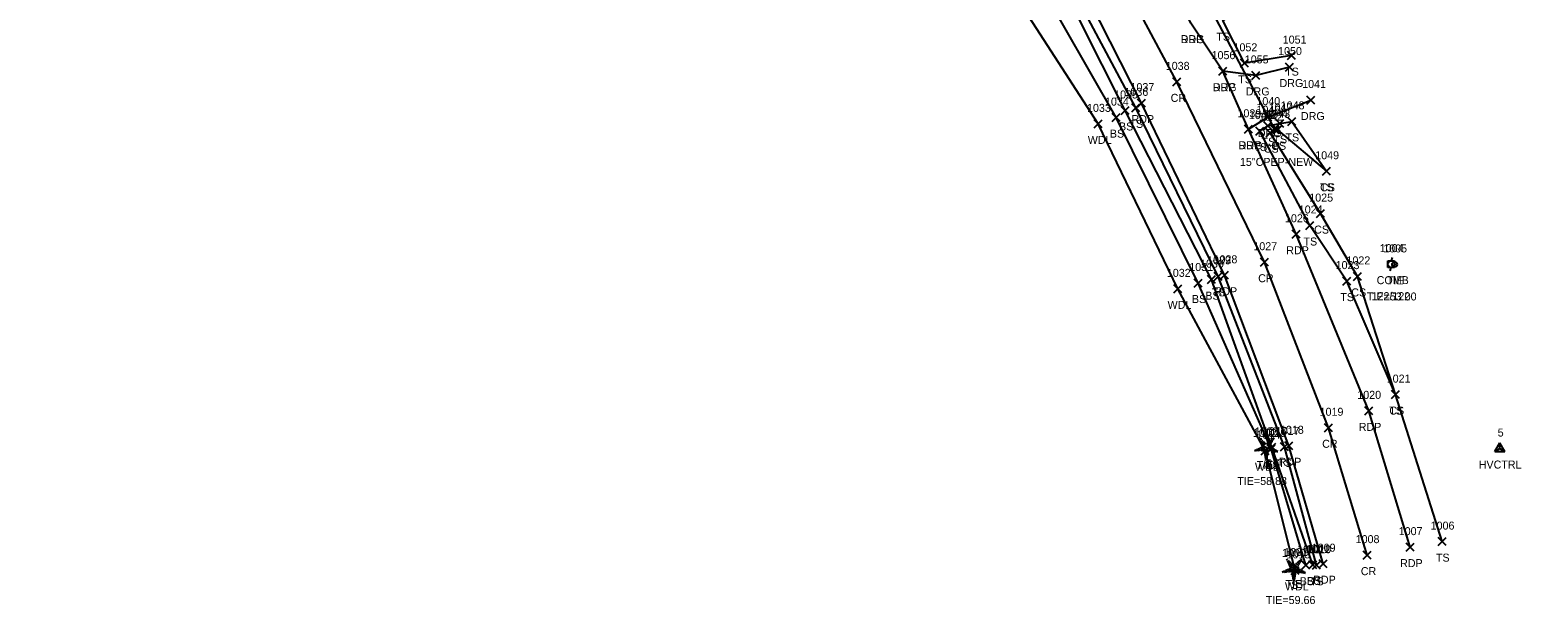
# Model space of a CAD drawing. Extents: x 1501299 to 1502485, y 381423 to 383765.
# Drawn here: x 1501626.4 to 1501999.1, y 382706.4 to 382849.9 of the extents above; entities that cross this region are included whole.
import ezdxf

# ---------------------------------------------------------------- set-up
doc = ezdxf.new("R2010")
doc.units = 0
for name, color, linetype in [('C_A', 7, 'Continuous'), ('C_C', 7, 'Continuous'), ('C_I', 7, 'Continuous'), ('CBP', 7, 'Continuous'), ('CPSM', 7, 'Continuous'), ('D_A', 7, 'Continuous'), ('D_C', 7, 'Continuous'), ('D_I', 7, 'Continuous'), ('D_TIC', 7, 'Continuous'), ('DCP', 7, 'Continuous'), ('L_A', 7, 'Continuous'), ('L_I', 7, 'Continuous'), ('L_TIC', 7, 'Continuous'), ('LAWA', 7, 'Continuous'), ('LELB', 7, 'Continuous'), ('LTC', 7, 'Continuous'), ('P_A', 7, 'Continuous'), ('P_I', 7, 'Continuous'), ('P_TIC', 7, 'Continuous'), ('PET', 7, 'Continuous'), ('PRC', 7, 'Continuous'), ('R_A', 7, 'Continuous'), ('R_I', 7, 'Continuous'), ('R_TIC', 7, 'Continuous'), ('RDG', 7, 'Continuous'), ('U_A', 7, 'Continuous'), ('U_C', 7, 'Continuous'), ('U_I', 7, 'Continuous'), ('UP', 7, 'Continuous')]:
    doc.layers.add(name, color=color, linetype=linetype)

msp = doc.modelspace()

# ---------------------------------------------------------------- linework, layer by layer
at = {"layer": 'CBP'}
for centre, radius in [((1501967.5, 382791.3), 0.625), ((1501967.5, 382791.3), 0.0833), ((1501934.94, 382745.18), 0.625), ((1501934.94, 382745.18), 0.0833), ((1501942.17, 382715.43), 0.625), ((1501942.17, 382715.43), 0.0833)]:
    msp.add_circle(centre, radius, dxfattribs=at)
at = {"layer": 'CPSM'}
for p, q in [((1501992.57, 382744.57), (1501993.82, 382746.73)), ((1501992.57, 382744.57), (1501993.82, 382745.29)), ((1501992.57, 382744.57), (1501995.07, 382744.57)), ((1501995.07, 382744.57), (1501993.82, 382746.73)), ((1501993.82, 382745.29), (1501993.82, 382746.73)), ((1501993.82, 382745.29), (1501993.82, 382745.29)), ((1501993.82, 382745.29), (1501995.07, 382744.57))]:
    msp.add_line(p, q, dxfattribs=at)
at = {"layer": 'D_TIC'}
for points in [[(1501936.68, 382823.93), (1501938.68, 382825.93)], [(1501938.68, 382823.93), (1501936.68, 382825.93)]]:
    msp.add_lwpolyline(points, dxfattribs=at)
at = {"layer": 'DCP'}
msp.add_lwpolyline([(1501937.68, 382824.93), (1501912.68, 382872.03)], dxfattribs=at)
at = {"layer": 'L_TIC'}
for points in [[(1501929, 382840.57), (1501931, 382842.57)], [(1501931, 382840.57), (1501929, 382842.57)], [(1501940.73, 382842.49), (1501942.73, 382844.49)], [(1501942.73, 382842.49), (1501940.73, 382844.49)], [(1501899.17, 382828.78), (1501901.17, 382830.78)], [(1501901.17, 382828.78), (1501899.17, 382830.78)], [(1501901.81, 382829.43), (1501903.81, 382831.43)], [(1501903.81, 382829.43), (1501901.81, 382831.43)], [(1501892.39, 382825.43), (1501894.39, 382827.43)], [(1501894.39, 382825.43), (1501892.39, 382827.43)], [(1501896.88, 382826.99), (1501898.88, 382828.99)], [(1501898.88, 382826.99), (1501896.88, 382828.99)], [(1501934.81, 382824.97), (1501936.81, 382826.97)], [(1501936.81, 382824.97), (1501934.81, 382826.97)], [(1501937.79, 382825.56), (1501939.79, 382827.56)], [(1501939.79, 382825.56), (1501937.79, 382827.56)], [(1501940.8, 382826.05), (1501942.8, 382828.05)], [(1501942.8, 382826.05), (1501940.8, 382828.05)], [(1501932.85, 382823.63), (1501934.85, 382825.63)], [(1501934.85, 382823.63), (1501932.85, 382825.63)], [(1501935.36, 382823.23), (1501937.36, 382825.23)], [(1501937.36, 382823.23), (1501935.36, 382825.23)], [(1501937.22, 382823.94), (1501939.22, 382825.94)], [(1501939.22, 382823.94), (1501937.22, 382825.94)], [(1501949.44, 382813.58), (1501951.44, 382815.58)], [(1501951.44, 382813.58), (1501949.44, 382815.58)], [(1501949.44, 382813.58), (1501951.44, 382815.58)], [(1501951.44, 382813.58), (1501949.44, 382815.58)], [(1501947.94, 382803.01), (1501949.94, 382805.01)], [(1501949.94, 382803.01), (1501947.94, 382805.01)], [(1501945.31, 382800.03), (1501947.31, 382802.03)], [(1501947.31, 382800.03), (1501945.31, 382802.03)], [(1501922.41, 382787.32), (1501924.41, 382789.32)], [(1501924.41, 382787.32), (1501922.41, 382789.32)], [(1501957.23, 382787.31), (1501959.23, 382789.31)], [(1501959.23, 382787.31), (1501957.23, 382789.31)], [(1501912.34, 382784.2), (1501914.34, 382786.2)], [(1501914.34, 382784.2), (1501912.34, 382786.2)], [(1501917.39, 382785.66), (1501919.39, 382787.66)], [(1501919.39, 382785.66), (1501917.39, 382787.66)], [(1501920.74, 382786.5), (1501922.74, 382788.5)], [(1501922.74, 382786.5), (1501920.74, 382788.5)], [(1501954.52, 382786.13), (1501956.52, 382788.13)], [(1501956.52, 382786.13), (1501954.52, 382788.13)], [(1501966.73, 382757.77), (1501968.73, 382759.77)], [(1501968.73, 382757.77), (1501966.73, 382759.77)], [(1501966.73, 382757.77), (1501968.73, 382759.77)], [(1501968.73, 382757.77), (1501966.73, 382759.77)], [(1501934.18, 382743.72), (1501936.18, 382745.72)], [(1501936.18, 382743.72), (1501934.18, 382745.72)], [(1501935.67, 382744.19), (1501937.67, 382746.19)], [(1501937.67, 382744.19), (1501935.67, 382746.19)], [(1501935.79, 382744.62), (1501937.79, 382746.62)], [(1501937.79, 382744.62), (1501935.79, 382746.62)], [(1501939, 382744.7), (1501941, 382746.7)], [(1501941, 382744.7), (1501939, 382746.7)], [(1501978.41, 382721.03), (1501980.41, 382723.03)], [(1501980.41, 382721.03), (1501978.41, 382723.03)], [(1501941.68, 382713.84), (1501943.68, 382715.84)], [(1501943.68, 382713.84), (1501941.68, 382715.84)], [(1501944.34, 382715.14), (1501946.34, 382717.14)], [(1501946.34, 382715.14), (1501944.34, 382717.14)], [(1501946.07, 382715.2), (1501948.07, 382717.2)], [(1501948.07, 382715.2), (1501946.07, 382717.2)], [(1501946.96, 382715.12), (1501948.96, 382717.12)], [(1501948.96, 382715.12), (1501946.96, 382717.12)]]:
    msp.add_lwpolyline(points, dxfattribs=at)
at = {"layer": 'LAWA'}
msp.add_lwpolyline([(1501942.68, 382714.84), (1501935.18, 382744.72), (1501913.34, 382785.2), (1501893.39, 382826.43), (1501865.29, 382869.92), (1501854.75, 382888.13), (1501835.93, 382927.55), (1501822.23, 382953.47), (1501796.61, 382993.04), (1501779.61, 383024.31), (1501754.16, 383064.05), (1501733.53, 383095.14)], dxfattribs=at)
at = {"layer": 'LELB'}
for points in [[(1501947.07, 382716.2), (1501936.79, 382745.62), (1501921.74, 382787.5), (1501900.17, 382829.78), (1501877.02, 382875.8), (1501866.17, 382892.91), (1501844.62, 382932.73), (1501828.06, 382959.04), (1501805.27, 382995.6), (1501783.69, 383028.16), (1501760.13, 383067.52), (1501734.81, 383103.88), (1501716.07, 383128.73), (1501702.98, 383136.28), (1501694.19, 383132.72)], [(1501947.96, 382716.12), (1501940, 382745.7), (1501923.41, 382788.32), (1501902.81, 382830.43), (1501868.96, 382893.88), (1501846.4, 382933.73), (1501830.03, 382960.15), (1501806.63, 382996.69), (1501785.68, 383029.2), (1501761.09, 383068.04), (1501736.24, 383105.32), (1501718.86, 383131.58)], [(1501945.34, 382716.14), (1501936.67, 382745.19), (1501918.39, 382786.66), (1501897.88, 382827.99), (1501871.61, 382874.07), (1501860.42, 382890.26), (1501841.87, 382931.65), (1501826.47, 382956.95), (1501803.66, 382993.76), (1501782.06, 383026.73), (1501758.57, 383066.64), (1501733.62, 383102.86), (1501712.41, 383124.49), (1501694.92, 383122.17), (1501687.27, 383121.66)], [(1501941.73, 382843.49), (1501930, 382841.57), (1501924.53, 382852.23), (1501934.69, 382858.69)], [(1501979.41, 382722.03), (1501967.73, 382758.77), (1501955.52, 382787.13), (1501946.31, 382801.03), (1501933.85, 382824.63), (1501935.81, 382825.97), (1501938.79, 382826.56), (1501941.8, 382827.05), (1501950.44, 382814.58)], [(1501967.73, 382758.77), (1501958.23, 382788.31), (1501948.94, 382804.01), (1501936.36, 382824.23), (1501938.22, 382824.94), (1501950.44, 382814.58)]]:
    msp.add_lwpolyline(points, dxfattribs=at)
at = {"layer": 'LTC'}
for p, q in [((1501933.55, 382747.76), (1501933.9, 382748.02)), ((1501936.94, 382748), (1501937.36, 382747.7)), ((1501932.58, 382745.04), (1501932.73, 382744.57)), ((1501933.03, 382745.26), (1501933.25, 382744.61)), ((1501933.49, 382745.48), (1501933.76, 382744.64)), ((1501933.76, 382747.3), (1501934.29, 382747.68)), ((1501933.95, 382745.69), (1501934.28, 382744.67)), ((1501933.97, 382746.83), (1501934.67, 382747.34)), ((1501934.18, 382746.37), (1501935.05, 382747)), ((1501934.4, 382745.91), (1501935.41, 382746.65)), ((1501934.4, 382745.91), (1501934.79, 382744.72)), ((1501936.02, 382744.72), (1501934.79, 382744.72)), ((1501935.98, 382744.22), (1501934.83, 382744.22)), ((1501935.41, 382746.65), (1501936.41, 382745.92)), ((1501935.83, 382746.96), (1501936.64, 382746.37)), ((1501936.41, 382745.92), (1501936.02, 382744.72)), ((1501936.2, 382747.31), (1501936.88, 382746.81)), ((1501936.85, 382745.65), (1501936.51, 382744.61)), ((1501936.57, 382747.66), (1501937.12, 382747.26)), ((1501937.29, 382745.4), (1501937, 382744.52)), ((1501937.74, 382745.15), (1501937.5, 382744.42)), ((1501938.18, 382744.9), (1501937.99, 382744.33)), ((1501935.9, 382743.72), (1501934.91, 382743.72)), ((1501935.81, 382743.22), (1501934.98, 382743.22)), ((1501935.73, 382742.72), (1501935.05, 382742.72)), ((1501939.49, 382714.7), (1501939.65, 382714.24)), ((1501939.95, 382714.92), (1501940.16, 382714.27)), ((1501940.41, 382715.14), (1501940.68, 382714.3)), ((1501940.46, 382717.43), (1501940.82, 382717.68)), ((1501940.67, 382716.96), (1501941.2, 382717.34)), ((1501940.86, 382715.35), (1501941.19, 382714.34)), ((1501940.88, 382716.49), (1501941.58, 382717.01)), ((1501941.09, 382716.03), (1501941.97, 382716.67)), ((1501941.32, 382715.57), (1501942.33, 382716.31)), ((1501941.32, 382715.57), (1501941.7, 382714.38)), ((1501942.93, 382714.38), (1501941.7, 382714.38)), ((1501942.33, 382716.31), (1501943.32, 382715.58)), ((1501942.75, 382716.62), (1501943.56, 382716.03)), ((1501943.32, 382715.58), (1501942.93, 382714.38)), ((1501943.12, 382716.97), (1501943.8, 382716.48)), ((1501943.76, 382715.31), (1501943.42, 382714.27)), ((1501943.49, 382717.32), (1501944.04, 382716.92)), ((1501943.86, 382717.67), (1501944.28, 382717.36)), ((1501944.21, 382715.06), (1501943.92, 382714.18)), ((1501944.65, 382714.81), (1501944.41, 382714.08)), ((1501945.09, 382714.56), (1501944.91, 382713.99)), ((1501942.89, 382713.88), (1501941.75, 382713.88)), ((1501942.81, 382713.38), (1501941.82, 382713.38)), ((1501942.73, 382712.88), (1501941.9, 382712.88)), ((1501942.64, 382712.38), (1501941.97, 382712.38))]:
    msp.add_line(p, q, dxfattribs=at)
at = {"layer": 'P_TIC'}
for points in [[(1501912.07, 382835.93), (1501914.07, 382837.93)], [(1501914.07, 382835.93), (1501912.07, 382837.93)], [(1501923.58, 382838.6), (1501925.58, 382840.6)], [(1501925.58, 382838.6), (1501923.58, 382840.6)], [(1501903.25, 382830.62), (1501905.25, 382832.62)], [(1501905.25, 382830.62), (1501903.25, 382832.62)], [(1501930, 382824.08), (1501932, 382826.08)], [(1501932, 382824.08), (1501930, 382826.08)], [(1501941.93, 382797.84), (1501943.93, 382799.84)], [(1501943.93, 382797.84), (1501941.93, 382799.84)], [(1501933.96, 382790.85), (1501935.96, 382792.85)], [(1501935.96, 382790.85), (1501933.96, 382792.85)], [(1501924.01, 382787.59), (1501926.01, 382789.59)], [(1501926.01, 382787.59), (1501924.01, 382789.59)], [(1501960.03, 382753.71), (1501962.03, 382755.71)], [(1501962.03, 382753.71), (1501960.03, 382755.71)], [(1501949.96, 382749.48), (1501951.96, 382751.48)], [(1501951.96, 382749.48), (1501949.96, 382751.48)], [(1501940.04, 382744.98), (1501942.04, 382746.98)], [(1501942.04, 382744.98), (1501940.04, 382746.98)], [(1501959.61, 382717.65), (1501961.61, 382719.65)], [(1501961.61, 382717.65), (1501959.61, 382719.65)], [(1501970.37, 382719.65), (1501972.37, 382721.65)], [(1501972.37, 382719.65), (1501970.37, 382721.65)], [(1501948.65, 382715.51), (1501950.65, 382717.51)], [(1501950.65, 382715.51), (1501948.65, 382717.51)]]:
    msp.add_lwpolyline(points, dxfattribs=at)
at = {"layer": 'PET'}
for points in [[(1501949.65, 382716.51), (1501941.04, 382745.98), (1501925.01, 382788.59), (1501904.25, 382831.62), (1501880.76, 382877.89), (1501870.56, 382894.72), (1501847.41, 382934.27), (1501830.94, 382961.01), (1501807.98, 382997.99), (1501787.08, 383029.95), (1501762.26, 383068.78), (1501737.38, 383106.29), (1501722.89, 383129.67), (1501696.7, 383166.34)], [(1501971.37, 382720.65), (1501961.03, 382754.71), (1501942.93, 382798.84), (1501931, 382825.08), (1501924.58, 382839.6), (1501916.53, 382851.6), (1501908.31, 382868.39), (1501899.17, 382885.53), (1501887.9, 382904.2), (1501878.51, 382922.49), (1501869.74, 382936.53), (1501858.07, 382956.49), (1501847.47, 382974.35), (1501824.87, 383010.25), (1501802.29, 383043.8), (1501787.99, 383066.09), (1501768.48, 383096.75)]]:
    msp.add_lwpolyline(points, dxfattribs=at)
at = {"layer": 'PRC'}
msp.add_lwpolyline([(1501960.61, 382718.65), (1501950.96, 382750.48), (1501934.96, 382791.85), (1501913.07, 382836.93), (1501889.31, 382881.38), (1501879.24, 382899.51), (1501856.39, 382940.32), (1501839.67, 382967), (1501816.06, 383004.31), (1501794.78, 383036.25), (1501769.81, 383075.16), (1501745.79, 383111.56), (1501729.43, 383136), (1501711.24, 383163.53), (1501694.82, 383188.2), (1501683.55, 383204), (1501664.64, 383231.24), (1501639.52, 383268.34), (1501626.39, 383287.88)], dxfattribs=at)
at = {"layer": 'R_TIC'}
for points in [[(1501940.24, 382839.63), (1501942.24, 382841.63)], [(1501942.24, 382839.63), (1501940.24, 382841.63)], [(1501923.58, 382838.6), (1501925.58, 382840.6)], [(1501925.58, 382838.6), (1501923.58, 382840.6)], [(1501931.82, 382837.54), (1501933.82, 382839.54)], [(1501933.82, 382837.54), (1501931.82, 382839.54)], [(1501945.59, 382831.39), (1501947.59, 382833.39)], [(1501947.59, 382831.39), (1501945.59, 382833.39)], [(1501934.81, 382827.11), (1501936.81, 382829.11)], [(1501936.81, 382827.11), (1501934.81, 382829.11)], [(1501930, 382824.08), (1501932, 382826.08)], [(1501932, 382824.08), (1501930, 382826.08)]]:
    msp.add_lwpolyline(points, dxfattribs=at)
at = {"layer": 'RDG'}
for points in [[(1501941.24, 382840.63), (1501932.82, 382838.54), (1501924.58, 382839.6)], [(1501931, 382825.08), (1501935.81, 382828.11), (1501946.59, 382832.39)]]:
    msp.add_lwpolyline(points, dxfattribs=at)
at = {"layer": 'UP'}
for p, q in [((1501966.88, 382793.04), (1501966.63, 382792.21)), ((1501965.79, 382790.54), (1501965.79, 382792.21)), ((1501965.79, 382792.21), (1501967.46, 382792.21)), ((1501967.46, 382790.54), (1501965.79, 382790.54)), ((1501966.38, 382789.71), (1501966.63, 382790.54)), ((1501966.63, 382791.37), (1501966.63, 382791.37)), ((1501967.46, 382792.21), (1501967.46, 382790.54))]:
    msp.add_line(p, q, dxfattribs=at)
msp.add_circle((1501966.63, 382791.37), 0.833, dxfattribs=at)

# ---------------------------------------------------------------- texts
at = {"layer": 'C_A'}
for s, p in [('TIE', (1501965.58, 382786.3)), ('TIE', (1501933.02, 382740.18)), ('HVCTRL', (1501988.52, 382740.29)), ('TIE', (1501940.24, 382710.43))]:
    msp.add_text(s, height=2, dxfattribs=at).set_placement(p)
at = {"layer": 'C_C'}
for s, p in [('TIE=53.00', (1501960.57, 382782.3)), ('TIE=58.88', (1501928.17, 382736.18)), ('TIE=59.66', (1501935.29, 382706.43))]:
    msp.add_text(s, height=2, dxfattribs=at).set_placement(p)
at = {"layer": 'C_I'}
for s, p in [('1005', (1501964.65, 382794.3)), ('1002', (1501932.09, 382748.18)), ('5', (1501993.26, 382748.29)), ('1001', (1501939.88, 382718.43))]:
    msp.add_text(s, height=2, dxfattribs=at).set_placement(p)
at = {"layer": 'D_A'}
msp.add_text('P', height=2, dxfattribs=at).set_placement((1501937.06, 382819.93))
at = {"layer": 'D_C'}
msp.add_text('15"CPEP-NEW', height=2, dxfattribs=at).set_placement((1501928.83, 382815.93))
at = {"layer": 'D_I'}
msp.add_text('1044', height=2, dxfattribs=at).set_placement((1501934.91, 382827.93))
at = {"layer": 'L_A'}
for s, p in [('TS', (1501922.94, 382847.23)), ('TS', (1501928.41, 382836.57)), ('TS', (1501940.14, 382838.49)), ('BS', (1501898.61, 382824.78)), ('TS', (1501901.22, 382825.43)), ('WDL', (1501890.81, 382821.43)), ('BS', (1501896.32, 382822.99)), ('TS', (1501934.22, 382820.97)), ('TS', (1501937.2, 382821.56)), ('TS', (1501940.21, 382822.05)), ('TS', (1501932.26, 382819.63)), ('CS', (1501934.8, 382819.23)), ('CS', (1501936.66, 382819.94)), ('TS', (1501948.85, 382809.58)), ('CS', (1501948.88, 382809.58)), ('CS', (1501947.38, 382799.01)), ('TS', (1501944.72, 382796.03)), ('TS', (1501921.82, 382783.32)), ('CS', (1501956.67, 382783.31)), ('WDL', (1501910.75, 382780.2)), ('BS', (1501916.83, 382781.66)), ('BS', (1501920.18, 382782.5)), ('TS', (1501953.93, 382782.13)), ('TS', (1501966.14, 382753.77)), ('CS', (1501966.17, 382753.77)), ('WDL', (1501932.6, 382739.72)), ('S', (1501934.74, 382740.56)), ('BS', (1501935.11, 382740.19)), ('BS', (1501935.23, 382740.62)), ('TS', (1501938.41, 382740.7)), ('TS', (1501977.82, 382717.03)), ('WDL', (1501940.09, 382709.84)), ('S', (1501941.65, 382710.22)), ('BS', (1501943.78, 382711.14)), ('BS', (1501945.51, 382711.2)), ('TS', (1501946.37, 382711.12))]:
    msp.add_text(s, height=2, dxfattribs=at).set_placement(p)
at = {"layer": 'L_I'}
for s, p in [('1051', (1501939.53, 382846.49)), ('1052', (1501927.23, 382844.57)), ('1035', (1501897.4, 382832.78)), ('1036', (1501899.98, 382833.43)), ('1033', (1501890.62, 382829.43)), ('1034', (1501895.11, 382830.99)), ('1046', (1501932.98, 382828.97)), ('1043', (1501935.44, 382827.94)), ('1047', (1501936.01, 382829.56)), ('1048', (1501939.03, 382830.05)), ('1045', (1501931.08, 382827.63)), ('1042', (1501933.59, 382827.23)), ('1049', (1501947.66, 382817.58)), ('1049', (1501947.66, 382817.58)), ('1025', (1501946.17, 382807.01)), ('1024', (1501943.54, 382804.03)), ('1029', (1501920.63, 382791.32)), ('1022', (1501955.46, 382791.31)), ('1032', (1501910.57, 382788.2)), ('1031', (1501916.18, 382789.66)), ('1030', (1501918.88, 382790.5)), ('1023', (1501952.75, 382790.13)), ('1021', (1501965.52, 382761.77)), ('1021', (1501965.52, 382761.77)), ('1003', (1501932.5, 382748.56)), ('1014', (1501932.98, 382747.72)), ('1015', (1501934.47, 382748.19)), ('1016', (1501934.53, 382748.62)), ('1017', (1501937.79, 382748.7)), ('1006', (1501976.5, 382725.03)), ('1000', (1501939.33, 382718.22)), ('1013', (1501940.47, 382717.84)), ('1012', (1501943.14, 382719.14)), ('1011', (1501945.43, 382719.2)), ('1010', (1501945.67, 382719.12))]:
    msp.add_text(s, height=2, dxfattribs=at).set_placement(p)
at = {"layer": 'LTC'}
for p in [(1501935.29, 382745.66), (1501942.21, 382715.32)]:
    msp.add_text('.', height=1.04, rotation=270, dxfattribs=at).set_placement(p)
at = {"layer": 'P_A'}
for s, p in [('RDP', (1501914.02, 382846.6)), ('CR', (1501911.51, 382831.93)), ('RDP', (1501922.06, 382834.6)), ('RDP', (1501901.74, 382826.62)), ('RDP', (1501928.49, 382820.08)), ('RDP', (1501940.41, 382793.84)), ('CR', (1501933.4, 382786.85)), ('RDP', (1501922.5, 382783.59)), ('RDP', (1501958.52, 382749.71)), ('CR', (1501949.39, 382745.48)), ('RDP', (1501938.53, 382740.98)), ('CR', (1501959.05, 382713.65)), ('RDP', (1501968.86, 382715.65)), ('RDP', (1501947.14, 382711.51))]:
    msp.add_text(s, height=2, dxfattribs=at).set_placement(p)
at = {"layer": 'P_I'}
for s, p in [('1038', (1501910.3, 382839.93)), ('1056', (1501921.75, 382842.6)), ('1037', (1501901.48, 382834.62)), ('1039', (1501928.22, 382828.08)), ('1026', (1501940.1, 382801.84)), ('1027', (1501932.19, 382794.85)), ('1028', (1501922.24, 382791.59)), ('1020', (1501958.17, 382757.71)), ('1019', (1501948.75, 382753.48)), ('1018', (1501938.84, 382748.98)), ('1007', (1501968.52, 382723.65)), ('1008', (1501957.76, 382721.65)), ('1009', (1501946.79, 382719.51))]:
    msp.add_text(s, height=2, dxfattribs=at).set_placement(p)
at = {"layer": 'R_A'}
for p in [(1501914.02, 382846.6), (1501938.73, 382835.63), (1501922.06, 382834.6), (1501930.31, 382833.54), (1501944.08, 382827.39), (1501933.3, 382823.11), (1501928.49, 382820.08)]:
    msp.add_text('DRG', height=2, dxfattribs=at).set_placement(p)
at = {"layer": 'R_I'}
for s, p in [('1050', (1501938.38, 382843.63)), ('1056', (1501921.75, 382842.6)), ('1055', (1501930.05, 382841.54)), ('1041', (1501944.39, 382835.39)), ('1039', (1501928.22, 382828.08)), ('1040', (1501932.95, 382831.11))]:
    msp.add_text(s, height=2, dxfattribs=at).set_placement(p)
at = {"layer": 'U_A'}
msp.add_text('COMB', height=2, dxfattribs=at).set_placement((1501963.01, 382786.37))
at = {"layer": 'U_C'}
msp.add_text('122/122', height=2, dxfattribs=at).set_placement((1501961.73, 382782.37))
at = {"layer": 'U_I'}
msp.add_text('1004', height=2, dxfattribs=at).set_placement((1501963.78, 382794.37))

doc.saveas('drawing.dxf')
